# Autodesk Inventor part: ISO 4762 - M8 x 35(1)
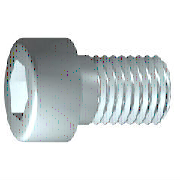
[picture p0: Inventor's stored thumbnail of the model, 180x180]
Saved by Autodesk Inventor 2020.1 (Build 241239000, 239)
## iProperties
Created: 2019-01
Part Number: ISO 4762 - M8 x 35(1)
Material: Edelstahl, 440C
Description: Innensechskantschraube
Document SubType Name: Modeling
Standard: ISO 4762
Designer: lutzd
Standard Revision: Fourth edition 2004-03-01
Standards Organization: ISO
Language: de-DE
Size Designation: M8 x 35
Categories: <MemberInstance><Categories><Category DisplayName="Verbindungselemente" InternalName="e4da775c-781d-43d5-af7c-5136215cf5a6" Mnemonic="FSTN"><Category DisplayNam
Mass: 20.6125 g
Surface Area: 15.3602 cm^2
Volume: 2.65968 cm^3
Density: 7.75 g/cm^3
Appearance: Halbpoliert
IsCustomPart: 0
Author: lutzd
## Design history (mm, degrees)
body "Solid1"
sketch "Skizze1"
  geometry: L1 (-2, 0)-(35, 0); L2 (35, 0)-(35, 4); L3 (35, 4)-(3.125, 4); L4 (3.125, 4)-(2.358, 4); L5 (2.358, 4)-(0, 4); L6 (0, 4)-(0, 6.5); L7 (0, 6.5)-(-8, 6.5); L8 (-8, 6.5)-(-8, 3.464); L9 (-8, 3.464)-(-4, 3.464); L10 (-4, 3.464)-(-2, 0); L11 (-16.6, 0)-(43.6, 0) reference; L12 (0, -1.3)-(0, 7.8) reference; L13 (3.125, 4)-(0, 4)
  constraints: 22 end point, 6 parallel, 2 collinear, 2 perpendicular, 1 horizontal, 1 point on line
  dimensions: "d1" = 31.875 distance from line of L3.end L2 (= GEL); "d2" = 0.76691 distance of L4.end L3.end (computed from GAL); "d3" = 8 distance between parallel lines of L8 L6 (= KOH); "d4" = 4 distance of L8.end L9.end (= INTI); "d5" = 60 deg angle of L10 L1; "d6" = 8 diameter of L3 L1 (= GD); "d7" = 8 diameter of L5 L1 (= BDM); "d8" = 6.9282 diameter of L9 L1 (= 1.1547 x SW); "d9" = 13 diameter of L7 L1 (= KOD); "d26" = 35 distance between parallel lines of L12 L2 (= NLG)
workplane "Work Plane1"
fillet "Fillet2" dims "d30" = 0.1 (= R)
revolve "Körper" stored, may be unused: angle "d10" = 90 deg
sketch "Skizze2"
  geometry: L1 (0, -9.1)-(0, 9.1) reference; L2 (-9.1, 0)-(9.1, 0) reference; L3 (3.464, 0)-(1.732, -3); L4 (1.732, -3)-(-1.732, -3); L5 (-1.732, -3)-(-3.464, 0); L6 (-3.464, 0)-(-1.732, 3); L7 (-1.732, 3)-(1.732, 3); L8 (1.732, 3)-(3.464, 0); 2 further points
  constraints: 12 end point, 1 coincident, 1 horizontal alignment, 1 point on line, 12 other
extrude "Loch" join sketch "Skizze2" stored distance "d11" = 10; taper "d12" = 0 deg
fillet "Rundung1" dims "d17" = 0.8 (= RR)
feature "Gewinde" dims "d13" = 31.875 (= GEL), "d14" = 0
chamfer "Fase1" distance "d15" = 0.76681 (= -0.5 x SPD + 0.5 x GD); stored, may be unused: second distance "d16" = 0.76681 (= GUL), angle "d27" = 45 deg
other parameters: "GD" = 8 [user parameter; used in 2 equation terms], "NLG" = 35 [user parameter; used in 1 equation term], "GEL" = 31.875 [user parameter; used in 2 equation terms], "KOD" = 13 [user parameter; used in 1 equation term], "KOH" = 8 [user parameter; used in 1 equation term], "INTI" = 4 [user parameter; used in 1 equation term], "GAL" = 0.76681 (= 0.61345 x PTC) [user parameter; used in 1 equation term], "GUL" = 0.76681 (= 0.61345 x PTC) [user parameter; used in 1 equation term], "BDM" = 8 (= NND) [user parameter; used in 1 equation term], "SW" = 6 [user parameter; used in 2 equation terms], "RR" = 0.8 [user parameter; used in 1 equation term], "SPD" = 6.46637 (= NND - 1.2269 x PTC) [user parameter; used in 1 equation term], "d19" = 0, "d28" = 0, "d29" = 0, "R" = 0.1 [user parameter; used in 1 equation term], "TOA" = 30 deg [user parameter], "GD1" = 6.46637 (= THREADDIA - 1.2269 x PTC) [user parameter], "THREADDIA" = 8 [user parameter; used in 1 equation term], "FAWI" = 45 deg [user parameter], "TPU" = 8 (computed from PTC) [user parameter], "PTC" = 1.25 [user parameter; used in 5 equation terms], "NND" = 8 [user parameter; used in 2 equation terms], "E0" = 6.93 (= 1.155 x SW) [user parameter]
